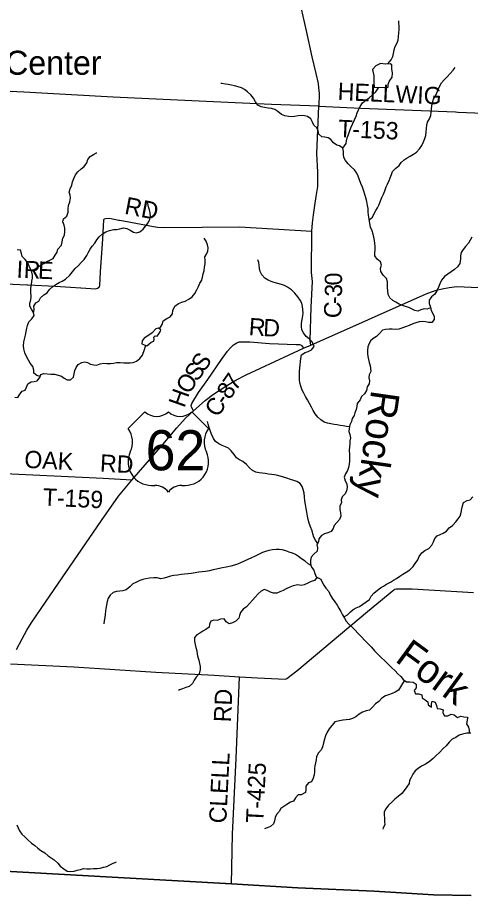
# Model space of a CAD drawing. Extents: x 1759416 to 2214760, y 252598 to 1116833.
# Drawn here: x 1994001 to 2001865, y 816522 to 831751 of the extents above; entities that cross this region are included whole.
import ezdxf

# ---------------------------------------------------------------- set-up
doc = ezdxf.new("R2010")
doc.units = 0
for name, color, linetype in [('GM_X_Adjacent_County', 7, 'Continuous'), ('GM_X_County', 7, 'Continuous'), ('GM_X_County_Road', 7, 'Continuous'), ('GM_X_County_Road_Text', 7, 'Continuous'), ('GM_X_Minor_Lake', 7, 'Continuous'), ('GM_X_Minor_River', 7, 'Continuous'), ('GM_X_Minor_River_Text', 7, 'Continuous'), ('GM_X_Township', 7, 'Continuous'), ('GM_X_Township_Road', 7, 'Continuous'), ('GM_X_Township_Road_Text', 7, 'Continuous'), ('GM_X_Unincorporated_Text', 7, 'Continuous'), ('GM_X_US_Location', 7, 'Continuous'), ('GM_X_US_Route', 7, 'Continuous'), ('GM_X_US_Shield', 7, 'Continuous')]:
    doc.layers.add(name, color=color, linetype=linetype)

msp = doc.modelspace()

# ---------------------------------------------------------------- linework, layer by layer
at = {"layer": 'GM_X_Adjacent_County'}
msp.add_lwpolyline([(2001880, 816522), (2001221, 816534), (2000194, 816593), (1998869, 816653), (1997718, 816724), (1993053, 816984), (1991541, 817066), (1991301, 817077), (1990962, 817091), (1990909, 817093), (1990797, 817097), (1990486, 817113), (1989752, 817152), (1988744, 817207), (1988298, 817233), (1986763, 817318), (1986195, 817348), (1985662, 817383)], dxfattribs=at)
at = {"layer": 'GM_X_County'}
msp.add_lwpolyline([(2001880, 816522), (2001221, 816534), (2000194, 816593), (1998869, 816653), (1997718, 816724), (1993053, 816984), (1991541, 817066), (1991301, 817077), (1990962, 817091), (1990909, 817093), (1990797, 817097), (1990486, 817113), (1989752, 817152), (1988744, 817207), (1988298, 817233), (1986763, 817318), (1986195, 817348), (1985662, 817383)], dxfattribs=at)
at = {"layer": 'GM_X_County_Road'}
for points in [[(1999092, 826069), (1999082, 826151), (1999099, 826728), (1999125, 827174), (1999105, 827327), (1999112, 828045), (1999122, 828188), (1999139, 828330), (1999162, 828488), (1999187, 828645), (1999217, 828819), (1999217, 829070), (1999196, 829394), (1999232, 830212), (1998408, 830243), (1997274, 830297), (1995661, 830373), (1994109, 830456), (1992550, 830530), (1991356, 830588)], [(1997058, 824929), (1997022, 824990), (1997018, 825024), (1997027, 825058), (1997143, 825245), (1997306, 825475), (1997545, 825822), (1997648, 825964), (1997692, 826016), (1997750, 826076), (1997807, 826109), (1997852, 826124), (1997904, 826126), (1998033, 826123), (1998378, 826098), (1998840, 826080), (1998899, 826078), (1998914, 826076), (1998925, 826068), (1998930, 826062), (1998966, 826014)]]:
    msp.add_lwpolyline(points, dxfattribs=at)
at = {"layer": 'GM_X_Minor_Lake'}
for points in [[(2000432, 830536), (2000436, 830554), (2000434, 830588), (2000453, 830644), (2000506, 830715), (2000509, 830787), (2000503, 830860), (2000502, 830930), (2000474, 830949), (2000392, 830945), (2000304, 830954), (2000220, 830913), (2000165, 830852), (2000186, 830742), (2000189, 830624), (2000196, 830546)], [(2000196, 830546), (2000432, 830536)], [(1996248, 826055), (1996283, 826086), (1996323, 826120), (1996365, 826139), (1996376, 826167), (1996368, 826209), (1996388, 826231), (1996428, 826226), (1996455, 826266), (1996481, 826308), (1996489, 826335), (1996448, 826360), (1996402, 826352), (1996337, 826281), (1996266, 826228), (1996202, 826191), (1996167, 826141), (1996159, 826093)], [(1996159, 826093), (1996248, 826055)]]:
    msp.add_lwpolyline(points, dxfattribs=at)
at = {"layer": 'GM_X_Minor_River'}
for points in [[(2000431, 830947), (2000489, 831020), (2000516, 831074), (2000530, 831129), (2000541, 831189), (2000560, 831249), (2000586, 831302), (2000609, 831358), (2000617, 831418), (2000624, 831486), (2000627, 831543), (2000625, 831601), (2000622, 831657), (2000622, 831695)], [(2000107, 828240), (2000162, 828291), (2000196, 828352), (2000221, 828402), (2000249, 828453), (2000280, 828511), (2000305, 828569), (2000329, 828630), (2000354, 828690), (2000377, 828747), (2000403, 828813), (2000424, 828863), (2000451, 828922), (2000473, 828972), (2000494, 829031), (2000514, 829083), (2000569, 829136), (2000625, 829186), (2000662, 829237), (2000714, 829282), (2000769, 829318), (2000821, 829347), (2000876, 829383), (2000930, 829418), (2000981, 829471), (2001021, 829529), (2001052, 829596), (2001073, 829654), (2001089, 829706), (2001098, 829767), (2001102, 829827), (2001105, 829885), (2001122, 829937), (2001154, 829992), (2001177, 830050), (2001184, 830111), (2001186, 830161), (2001193, 830217), (2001207, 830273), (2001224, 830334), (2001250, 830384), (2001281, 830444), (2001306, 830503), (2001336, 830567), (2001365, 830618), (2001410, 830670), (2001460, 830725), (2001513, 830780), (2001565, 830836), (2001602, 830883)], [(2001173, 826713), (2001115, 826695), (2001061, 826698), (2001005, 826678), (2000950, 826655), (2000897, 826669), (2000843, 826700), (2000793, 826724), (2000735, 826737), (2000683, 826757), (2000628, 826782), (2000568, 826816), (2000516, 826845), (2000463, 826889), (2000439, 826949), (2000430, 827009), (2000423, 827065), (2000426, 827165), (2000406, 827227), (2000349, 827285), (2000308, 827348), (2000306, 827398), (2000321, 827455), (2000301, 827515), (2000246, 827562), (2000204, 827618), (2000203, 827670), (2000212, 827720), (2000212, 827774), (2000203, 827835), (2000197, 827885), (2000190, 827939), (2000176, 827991), (2000157, 828049), (2000132, 828115), (2000118, 828179), (2000105, 828251), (2000094, 828321), (2000091, 828383), (2000089, 828439), (2000080, 828491), (2000065, 828559), (2000049, 828623), (2000032, 828683), (2000016, 828741), (1999993, 828807), (1999964, 828875), (1999937, 828937), (1999915, 828997), (1999894, 829051), (1999854, 829108), (1999795, 829164), (1999743, 829211), (1999694, 829271), (1999669, 829323), (1999661, 829377), (1999658, 829429), (1999648, 829487), (1999593, 829525), (1999543, 829540), (1999489, 829580), (1999442, 829635), (1999392, 829663), (1999336, 829678), (1999284, 829684), (1999231, 829730), (1999219, 829784), (1999198, 829837), (1999144, 829887), (1999121, 829939), (1999094, 829995), (1999036, 830032), (1998986, 830046), (1998934, 830051), (1998876, 830045), (1998810, 830034), (1998754, 830027), (1998704, 830035), (1998640, 830048), (1998584, 830070), (1998521, 830121), (1998469, 830155), (1998411, 830172), (1998355, 830180), (1998291, 830189), (1998232, 830205), (1998176, 830234), (1998132, 830292), (1998097, 830352), (1998050, 830411), (1997994, 830465), (1997941, 830504), (1997887, 830532), (1997829, 830551), (1997771, 830565), (1997715, 830576), (1997661, 830588), (1997609, 830595), (1997546, 830605), (1997528, 830608)], [(1999648, 829487), (1999709, 829564), (1999714, 829614), (1999726, 829664), (1999745, 829723), (1999767, 829777), (1999790, 829836), (1999815, 829902), (1999852, 829979), (1999880, 830041), (1999901, 830099), (1999920, 830152), (1999948, 830210), (1999993, 830269), (2000051, 830317), (2000108, 830358), (2000166, 830409), (2000221, 830464), (2000256, 830514), (2000274, 830542)], [(1994238, 827360), (1994288, 827383), (1994340, 827417), (1994393, 827450), (1994455, 827487), (1994511, 827517), (1994564, 827540), (1994622, 827571), (1994653, 827629), (1994689, 827680), (1994702, 827734), (1994765, 827801), (1994773, 827863), (1994790, 827923), (1994814, 827978), (1994821, 828038), (1994822, 828098), (1994812, 828150), (1994785, 828206), (1994797, 828260), (1994856, 828307), (1994879, 828373), (1994881, 828432), (1994884, 828492), (1994909, 828554), (1994919, 828621), (1994914, 828671), (1994896, 828725), (1994913, 828781), (1994942, 828841), (1994958, 828902), (1994979, 828962), (1995008, 829020), (1995048, 829075), (1995103, 829126), (1995155, 829170), (1995204, 829233), (1995223, 829287), (1995263, 829342), (1995318, 829377), (1995370, 829405), (1995378, 829407)], [(1994280, 826624), (1994288, 826685), (1994281, 826747), (1994318, 826802), (1994370, 826832), (1994397, 826889), (1994455, 826939), (1994514, 826974), (1994558, 827035), (1994613, 827087), (1994665, 827120), (1994722, 827153), (1994776, 827177), (1994834, 827212), (1994909, 827281), (1994954, 827342), (1995002, 827398), (1995057, 827451), (1995107, 827504), (1995160, 827556), (1995205, 827623), (1995233, 827683), (1995260, 827734), (1995297, 827786), (1995341, 827837), (1995376, 827893), (1995420, 827948), (1995471, 827995), (1995535, 828035), (1995598, 828060), (1995666, 828075), (1995722, 828075), (1995776, 828084), (1995838, 828101), (1995900, 828089), (1995956, 828064), (1996013, 828030), (1996069, 828015), (1996124, 828035), (1996180, 828082), (1996225, 828135), (1996267, 828191), (1996300, 828252), (1996310, 828302), (1996301, 828364), (1996290, 828418), (1996276, 828470), (1996265, 828524), (1996257, 828566)], [(1996464, 826350), (1996510, 826425), (1996531, 826489), (1996592, 826528), (1996650, 826557), (1996690, 826611), (1996697, 826670), (1996732, 826742), (1996798, 826791), (1996853, 826816), (1996913, 826834), (1996973, 826863), (1997032, 826908), (1997078, 826964), (1997115, 827025), (1997142, 827083), (1997166, 827142), (1997201, 827196), (1997210, 827250), (1997226, 827307), (1997239, 827359), (1997249, 827421), (1997256, 827481), (1997259, 827542), (1997255, 827598), (1997280, 827648), (1997308, 827701), (1997313, 827757), (1997300, 827811), (1997276, 827873), (1997241, 827924), (1997239, 827926)], [(2001887, 827944), (2001860, 827892), (2001831, 827839), (2001779, 827782), (2001736, 827730), (2001706, 827675), (2001695, 827615), (2001692, 827565), (2001678, 827483), (2001643, 827426), (2001586, 827381), (2001530, 827341), (2001470, 827298), (2001415, 827257), (2001364, 827193), (2001334, 827132), (2001311, 827072), (2001284, 827013), (2001244, 826955), (2001191, 826904), (2001151, 826846), (2001150, 826789), (2001169, 826729), (2001185, 826670), (2001212, 826618), (2001234, 826566), (2001237, 826516), (2001194, 826463), (2001136, 826460), (2001086, 826470), (2001029, 826477), (2000972, 826471), (2000918, 826458), (2000864, 826438), (2000802, 826411), (2000739, 826386), (2000619, 826345), (2000557, 826340), (2000507, 826348), (2000451, 826345), (2000393, 826341), (2000337, 826328), (2000284, 826271), (2000236, 826219), (2000185, 826188), (2000133, 826151), (2000104, 826099), (2000082, 826037), (2000077, 825976), (2000078, 825922), (2000086, 825872), (2000097, 825822), (2000109, 825770), (2000124, 825716), (2000130, 825662), (2000133, 825610), (2000108, 825552), (2000098, 825499), (2000111, 825449), (2000107, 825399), (2000074, 825345), (2000059, 825282), (2000027, 825226), (1999972, 825177)], [(1994394, 825523), (1994338, 825542), (1994285, 825582), (1994285, 825636), (1994264, 825696), (1994220, 825756), (1994154, 825871), (1994126, 825937), (1994109, 826003), (1994102, 826059), (1994110, 826124), (1994138, 826244), (1994148, 826305), (1994161, 826361), (1994175, 826411), (1994198, 826472), (1994247, 826524), (1994289, 826581), (1994278, 826637), (1994242, 826691), (1994217, 826746), (1994214, 826797), (1994232, 826857), (1994239, 826907), (1994230, 826991), (1994234, 827055), (1994241, 827116), (1994248, 827180), (1994262, 827230), (1994263, 827282), (1994251, 827334), (1994224, 827386), (1994202, 827440), (1994177, 827496), (1994132, 827552), (1994080, 827605), (1994069, 827659), (1994051, 827717), (1993997, 827723)], [(1999765, 824649), (1999713, 824659), (1999657, 824671), (1999603, 824676), (1999553, 824684), (1999499, 824693), (1999443, 824703), (1999383, 824714), (1999327, 824733), (1999268, 824773), (1999216, 824819), (1999169, 824876), (1999135, 824936), (1999104, 824994), (1999071, 825058), (1999035, 825121), (1999002, 825177), (1998973, 825233), (1998945, 825287), (1998918, 825355), (1998904, 825415), (1998897, 825475), (1998898, 825541), (1998899, 825611), (1998903, 825672), (1998908, 825726), (1998916, 825782), (1998921, 825838), (1998934, 825902), (1998996, 825939), (1999048, 825960), (1999107, 825988), (1999151, 826045), (1999114, 826125), (1999067, 826177), (1999015, 826218), (1998968, 826282), (1998938, 826334), (1998929, 826394), (1998932, 826452), (1998946, 826516), (1998955, 826574), (1998959, 826625), (1998956, 826685), (1998949, 826739), (1998935, 826795), (1998908, 826847), (1998868, 826904), (1998817, 826968), (1998756, 827026), (1998688, 827073), (1998638, 827101), (1998583, 827122), (1998523, 827140), (1998457, 827155), (1998405, 827170), (1998353, 827194), (1998296, 827233), (1998242, 827289), (1998211, 827345), (1998203, 827399), (1998198, 827453), (1998191, 827503), (1998171, 827549)], [(1993954, 825166), (1994004, 825162), (1994041, 825217), (1994081, 825269), (1994133, 825286), (1994158, 825340), (1994179, 825396), (1994235, 825429), (1994287, 825440), (1994341, 825450), (1994390, 825509), (1994406, 825561), (1994457, 825574), (1994581, 825567), (1994645, 825564), (1994706, 825548), (1994762, 825529), (1994812, 825495), (1994862, 825464), (1994918, 825468), (1994970, 825515), (1994983, 825573), (1994995, 825629), (1995016, 825680), (1995052, 825732), (1995115, 825769), (1995167, 825780), (1995217, 825766), (1995267, 825741), (1995323, 825725), (1995378, 825722), (1995435, 825742), (1995499, 825755), (1995549, 825749), (1995613, 825750), (1995669, 825757), (1995721, 825765), (1995785, 825766), (1995845, 825760), (1995903, 825759), (1995959, 825762), (1996011, 825770), (1996067, 825791), (1996124, 825836), (1996169, 825892), (1996208, 825993), (1996223, 826049), (1996221, 826067)], [(1999972, 825177), (1999950, 825121), (1999899, 825058), (1999892, 825006), (1999882, 824950), (1999857, 824895), (1999847, 824845), (1999814, 824795), (1999802, 824742), (1999771, 824684), (1999760, 824622), (1999754, 824571), (1999769, 824519), (1999785, 824461), (1999768, 824409), (1999769, 824359), (1999765, 824307), (1999760, 824243), (1999767, 824178), (1999767, 824110), (1999764, 824058), (1999758, 824002), (1999747, 823946), (1999730, 823891), (1999696, 823833), (1999671, 823776), (1999691, 823716), (1999718, 823661), (1999725, 823601), (1999715, 823538), (1999692, 823488), (1999640, 823439), (1999619, 823383), (1999628, 823333), (1999596, 823280), (1999595, 823218), (1999607, 823162), (1999612, 823102), (1999593, 823044), (1999547, 822991), (1999498, 822940), (1999480, 822886), (1999447, 822836), (1999391, 822815), (1999333, 822796), (1999276, 822768), (1999230, 822709), (1999227, 822657), (1999200, 822605), (1999208, 822550), (1999201, 822492), (1999143, 822440), (1999100, 822389), (1999085, 822331), (1999089, 822273), (1999106, 822217), (1999148, 822163), (1999161, 822105), (1999184, 822051), (1999268, 822010), (1999292, 821956), (1999321, 821904), (1999356, 821852), (1999404, 821797), (1999431, 821739), (1999465, 821681), (1999510, 821615), (1999549, 821557), (1999579, 821506), (1999616, 821446), (1999644, 821390), (1999677, 821332), (1999708, 821278), (1999754, 821227), (1999811, 821173), (1999861, 821123), (1999910, 821072), (1999974, 821006), (2000033, 820947), (2000092, 820889), (2000146, 820830), (2000201, 820766), (2000264, 820700), (2000316, 820649), (2000377, 820591), (2000437, 820536), (2000494, 820474), (2000557, 820417), (2000607, 820365), (2000658, 820321), (2000698, 820266), (2000756, 820228), (2000812, 820229), (2000869, 820219), (2000921, 820186), (2000922, 820126), (2000890, 820075), (2000911, 820021), (2000967, 820018), (2001019, 820004), (2001027, 819952)], [(1999213, 822629), (1999173, 822686), (1999148, 822738), (1999130, 822796), (1999115, 822848), (1999090, 822916), (1999066, 822982), (1999049, 823042), (1999034, 823104), (1999022, 823168), (1999011, 823234), (1999000, 823304), (1998989, 823366), (1998983, 823439), (1998976, 823503), (1998963, 823565), (1998943, 823617), (1998906, 823668), (1998850, 823704), (1998796, 823721), (1998740, 823739), (1998675, 823760), (1998617, 823780), (1998521, 823805), (1998461, 823816), (1998357, 823831), (1998303, 823839), (1998251, 823846), (1998199, 823852), (1998140, 823865), (1998078, 823892), (1998026, 823942), (1997975, 824000), (1997915, 824049), (1997856, 824077), (1997804, 824112), (1997761, 824170), (1997713, 824234), (1997662, 824279), (1997612, 824303), (1997552, 824330), (1997497, 824354), (1997439, 824399), (1997404, 824451), (1997370, 824525), (1997347, 824587), (1997330, 824641), (1997312, 824699), (1997299, 824743)], [(1999664, 821355), (1999728, 821389), (1999780, 821439), (1999831, 821480), (1999883, 821509), (1999937, 821535), (1999994, 821572), (2000054, 821615), (2000111, 821657), (2000143, 821712), (2000188, 821768), (2000250, 821819), (2000301, 821856), (2000355, 821888), (2000406, 821919), (2000476, 821958), (2000530, 821991), (2000581, 822021), (2000639, 822062), (2000691, 822094), (2000748, 822127), (2000810, 822170), (2000871, 822229), (2000908, 822281), (2000950, 822342), (2000977, 822400), (2001022, 822463), (2001076, 822503), (2001140, 822542), (2001193, 822599), (2001222, 822655), (2001248, 822712), (2001289, 822762), (2001341, 822785), (2001393, 822804), (2001452, 822840), (2001494, 822899), (2001553, 822942), (2001610, 823002), (2001652, 823053), (2001685, 823103), (2001705, 823164), (2001716, 823230), (2001727, 823282), (2001747, 823339), (2001808, 823371), (2001862, 823384), (2001908, 823436)], [(1999097, 822246), (1999045, 822276), (1998995, 822320), (1998934, 822363), (1998882, 822401), (1998828, 822434), (1998773, 822460), (1998719, 822479), (1998659, 822499), (1998595, 822516), (1998545, 822522), (1998493, 822523), (1998427, 822516), (1998367, 822506), (1998309, 822487), (1998253, 822469), (1998184, 822436), (1998118, 822403), (1998062, 822376), (1997999, 822348), (1997937, 822319), (1997873, 822290), (1997822, 822270), (1997768, 822251), (1997706, 822236), (1997650, 822224), (1997532, 822200), (1997455, 822182), (1997397, 822169), (1997335, 822154), (1997267, 822140), (1997209, 822133), (1997151, 822128), (1997086, 822120), (1997018, 822109), (1996958, 822102), (1996902, 822096), (1996844, 822087), (1996776, 822080), (1996716, 822072), (1996658, 822061), (1996606, 822045), (1996547, 822024), (1996487, 822017), (1996425, 822033), (1996365, 822034), (1996293, 822023), (1996231, 822013), (1996177, 822000), (1996125, 821987), (1996064, 821959), (1996004, 821928), (1995951, 821875), (1995885, 821825), (1995831, 821808), (1995775, 821801), (1995718, 821793), (1995660, 821780), (1995608, 821730), (1995577, 821679), (1995557, 821619), (1995546, 821558), (1995533, 821502), (1995527, 821452), (1995524, 821396), (1995514, 821342), (1995505, 821283), (1995498, 821231)], [(1999201, 822042), (1999156, 821988), (1999100, 821968), (1999043, 821941), (1998979, 821910), (1998923, 821900), (1998869, 821909), (1998785, 821892), (1998728, 821870), (1998666, 821841), (1998614, 821812), (1998557, 821788), (1998501, 821765), (1998447, 821763), (1998395, 821782), (1998338, 821814), (1998286, 821827), (1998233, 821799), (1998181, 821752), (1998126, 821697), (1998080, 821645), (1998031, 821584), (1997978, 821527), (1997920, 821487), (1997873, 821430), (1997855, 821380), (1997842, 821329), (1997792, 821277), (1997735, 821252), (1997675, 821235), (1997624, 821267), (1997586, 821319), (1997524, 821314), (1997466, 821291), (1997410, 821295), (1997356, 821282), (1997335, 821228), (1997328, 821178), (1997272, 821137), (1997220, 821106), (1997167, 821074), (1997113, 821045), (1997074, 820995), (1997076, 820932), (1997085, 820876), (1997097, 820822), (1997112, 820764), (1997121, 820710), (1997131, 820656), (1997146, 820604), (1997160, 820548), (1997171, 820496), (1997173, 820444), (1997152, 820366), (1997103, 820309), (1997070, 820255), (1997040, 820200), (1996979, 820147), (1996921, 820127), (1996867, 820106), (1996813, 820086), (1996795, 820079)], [(2000722, 820250), (2000687, 820197), (2000653, 820141), (2000614, 820084), (2000560, 820048), (2000507, 820027), (2000445, 820004), (2000391, 819984), (2000326, 819943), (2000272, 819888), (2000217, 819844), (2000163, 819787), (2000112, 819738), (2000052, 819722), (1999992, 819701), (1999931, 819666), (1999873, 819620), (1999816, 819589), (1999764, 819576), (1999708, 819570), (1999654, 819563), (1999651, 819562)], [(2001027, 819952), (2001078, 819913), (2001128, 819883), (2001133, 819829), (2001187, 819788), (2001187, 819840), (2001202, 819892), (2001254, 819872), (2001277, 819817), (2001287, 819762), (2001339, 819759), (2001390, 819739), (2001388, 819687), (2001417, 819635), (2001471, 819638), (2001528, 819669), (2001584, 819653), (2001641, 819606), (2001697, 819630), (2001749, 819619), (2001807, 819617), (2001820, 819598)], [(1999651, 819562), (1999511, 819534), (1999413, 819410), (1999379, 819354), (1999347, 819289), (1999333, 819231), (1999313, 819169), (1999301, 819118), (1999279, 819054), (1999228, 818993), (1999192, 818933), (1999184, 818877), (1999172, 818825), (1999164, 818773), (1999158, 818723), (1999155, 818664), (1999153, 818612), (1999133, 818556), (1999105, 818492), (1999053, 818473), (1999009, 818415), (1999007, 818359), (1999000, 818305), (1998924, 818269), (1998873, 818265), (1998826, 818213), (1998794, 818157), (1998738, 818141), (1998676, 818098), (1998626, 818062), (1998574, 818030), (1998542, 817978), (1998498, 817926), (1998472, 817874), (1998462, 817818), (1998444, 817764), (1998393, 817718), (1998333, 817692), (1998291, 817676)], [(2001851, 819336), (2001848, 819388), (2001838, 819442), (2001804, 819496), (2001820, 819598)], [(2001870, 819336), (2001800, 819334), (2001726, 819317), (2001672, 819301), (2001614, 819263), (2001546, 819231), (2001496, 819181), (2001442, 819119), (2001391, 819069), (2001329, 819004), (2001267, 818942), (2001215, 818896), (2001151, 818838), (2001087, 818798), (2001017, 818764), (2000959, 818726), (2000905, 818685), (2000863, 818627), (2000837, 818567), (2000809, 818515), (2000800, 818465), (2000758, 818403), (2000716, 818343), (2000672, 818289), (2000612, 818237), (2000554, 818189), (2000498, 818137), (2000440, 818086), (2000394, 818026), (2000365, 817974), (2000365, 817920), (2000371, 817864), (2000373, 817803), (2000377, 817745), (2000347, 817693), (2000342, 817671)], [(1993990, 817747), (1994012, 817693), (1994034, 817643), (1994073, 817586), (1994129, 817536), (1994181, 817484), (1994243, 817428), (1994302, 817387), (1994354, 817339), (1994406, 817301), (1994472, 817261), (1994532, 817211), (1994583, 817174), (1994637, 817138), (1994699, 817082), (1994743, 817032), (1994806, 816981), (1994860, 816945), (1994920, 816939), (1994982, 816945), (1995034, 816961), (1995096, 816970), (1995148, 816988), (1995204, 816984), (1995264, 816982), (1995322, 816990), (1995382, 816989), (1995433, 816997), (1995495, 817013), (1995553, 817025), (1995603, 817051), (1995659, 817079), (1995711, 817100), (1995705, 817100)]]:
    msp.add_lwpolyline(points, dxfattribs=at)
at = {"layer": 'GM_X_Township'}
msp.add_lwpolyline([(2001880, 816522), (2001221, 816534), (2000194, 816593), (1998869, 816653), (1997718, 816724), (1993053, 816984), (1991541, 817066), (1991301, 817077), (1990962, 817091), (1990909, 817093), (1990797, 817097), (1990486, 817113), (1989752, 817152), (1988744, 817207), (1988298, 817233), (1986763, 817318), (1986195, 817348), (1985662, 817383)], dxfattribs=at)
at = {"layer": 'GM_X_Township_Road'}
for points in [[(1998868, 832161), (1999013, 831519), (1999111, 831068), (1999181, 830779), (1999221, 830609), (1999229, 830531), (1999237, 830436), (1999232, 830212)], [(1999232, 830212), (1999959, 830178), (2001605, 830113), (2001649, 830112)], [(2001649, 830112), (2001652, 830111), (2002384, 830080)], [(1994177, 827113), (1994660, 827089), (1995360, 827044), (1995392, 827054), (1995416, 827072), (1995430, 827104), (1995444, 827340), (1995481, 827914), (1995497, 828240), (1995507, 828258), (1995529, 828268), (1995597, 828270), (1995758, 828239), (1995774, 828236)], [(1995774, 828236), (1995843, 828222), (1996361, 828127), (1996431, 828115), (1996557, 828109), (1997853, 828118), (1999112, 828045)], [(1992157, 827209), (1992767, 827176), (1993664, 827138), (1994170, 827113), (1994177, 827113)], [(1995988, 823727), (1995488, 823755), (1993652, 823842), (1992798, 823872), (1992158, 823903)], [(1993881, 820538), (1994981, 820489), (1996401, 820395), (1997413, 820343), (1997857, 820313), (1998169, 820299), (1998651, 820275), (1998679, 820283), (1998853, 820419), (2000079, 821445), (2000532, 821826), (2000550, 821836), (2000578, 821842), (2000852, 821842), (2001919, 821780)], [(1997718, 816724), (1997731, 817585), (1997798, 818895), (1997857, 820313)], [(1993053, 816984), (1997718, 816724), (1998869, 816653), (2000194, 816593), (2001221, 816534), (2001880, 816522)]]:
    msp.add_lwpolyline(points, dxfattribs=at)
at = {"layer": 'GM_X_US_Route'}
msp.add_lwpolyline([(1993985, 820787), (1994083, 820976), (1994162, 821125), (1994237, 821245), (1994409, 821500), (1994636, 821828), (1995460, 823027), (1995753, 823448), (1995988, 823727), (1996521, 824346), (1996769, 824632), (1996920, 824800), (1997058, 824929), (1997259, 825106), (1997404, 825218), (1997616, 825356), (1997791, 825458), (1997973, 825554), (1998966, 826014), (1999092, 826069), (2001095, 826956), (2001190, 826992), (2001275, 827023), (2001376, 827043), (2001498, 827071), (2001628, 827085), (2002505, 827048)], dxfattribs=at)
at = {"layer": 'GM_X_US_Shield'}
for p, q in [((1996213, 824912), (1995923, 824622)), ((1997316, 824622), (1997026, 824912)), ((1996329, 823636), (1996387, 823636)), ((1996852, 823636), (1996910, 823636))]:
    msp.add_line(p, q, dxfattribs=at)
for centre, radius, start, end in [((1996417, 825120), 290, 225.573, 314.427), ((1996823, 825120), 290, 225.573, 314.427), ((1995591, 824389), 406, 334.5471, 35.0009), ((1997648, 824389), 406, 144.9991, 205.4529), ((1996325, 824042), 406, 154.8319, 270.6383), ((1996914, 824042), 406, 269.3617, 25.1681), ((1996387, 823346), 290, 36.8699, 90), ((1996852, 823346), 290, 90, 143.1301)]:
    msp.add_arc(centre, radius, start, end, dxfattribs=at)

# ---------------------------------------------------------------- texts
at = {"layer": 'GM_X_County_Road_Text'}
for s, rotation, p in [('0', 91.6987, (1999639, 827108)), ('3', 88.0712, (1999633, 826903)), ('-', 87.6713, (1999628, 826777)), ('C', 87.5755, (1999617, 826530)), ('R', 356.0626, (1998009, 826243)), ('D', 357.1397, (1998261, 826226)), ('S', 55.0381, (1997236, 825585)), ('S', 55.137, (1997121, 825419)), ('7', 55.0845, (1997788, 825259)), ('O', 56.806, (1996978, 825200)), ('H', 70.3854, (1996897, 824968)), ('8', 55.2533, (1997683, 825107)), ('C', 57.608, (1997483, 824800)), ('-', 55.8553, (1997614, 825006))]:
    msp.add_text(s, height=300, rotation=rotation, dxfattribs=at).set_placement(p)
at = {"layer": 'GM_X_Minor_River_Text'}
for s, rotation, p in [('Rocky', 261.8353, (2000146, 825303)), ('Fork', 323.8365, (2000537, 820593))]:
    msp.add_text(s, height=500, rotation=rotation, dxfattribs=at).set_placement(p)
at = {"layer": 'GM_X_Township_Road_Text'}
for s, rotation, p in [('HELLWIG', 357.4461, (1999555, 830322)), ('T-153', 357.4721, (1999564, 829680)), ('RD', 349.0774, (1995845, 828349)), ('I', 357.0841, (1993978, 827239)), ('R', 357.5712, (1994104, 827233)), ('E', 357.6621, (1994351, 827222)), ('OAK', 357.0034, (1994113, 823942)), ('RD', 357.0396, (1995427, 823876)), ('T-159', 357.1936, (1994434, 823287)), ('RD', 87.5313, (1997707, 819522)), ('CLELL', 87.1153, (1997624, 817767)), ('T-425', 87.1941, (1998266, 817775))]:
    msp.add_text(s, height=300, rotation=rotation, dxfattribs=at).set_placement(p)
at = {"layer": 'GM_X_Unincorporated_Text'}
msp.add_text('Morgan Center', height=417, rotation=0, dxfattribs=at).set_placement((1991740, 830759))
at = {"layer": 'GM_X_US_Location'}
for s in ['0', '/']:
    msp.add_text(s, height=1, dxfattribs=at).set_placement((1996619, 824240))
msp.add_text('62', height=1, rotation=0, dxfattribs=at).set_placement((1996413, 824033))
at = {"layer": 'GM_X_US_Shield'}
msp.add_text('62', height=696.1, dxfattribs=at).set_placement((1996225, 823897))

doc.saveas('drawing.dxf')
